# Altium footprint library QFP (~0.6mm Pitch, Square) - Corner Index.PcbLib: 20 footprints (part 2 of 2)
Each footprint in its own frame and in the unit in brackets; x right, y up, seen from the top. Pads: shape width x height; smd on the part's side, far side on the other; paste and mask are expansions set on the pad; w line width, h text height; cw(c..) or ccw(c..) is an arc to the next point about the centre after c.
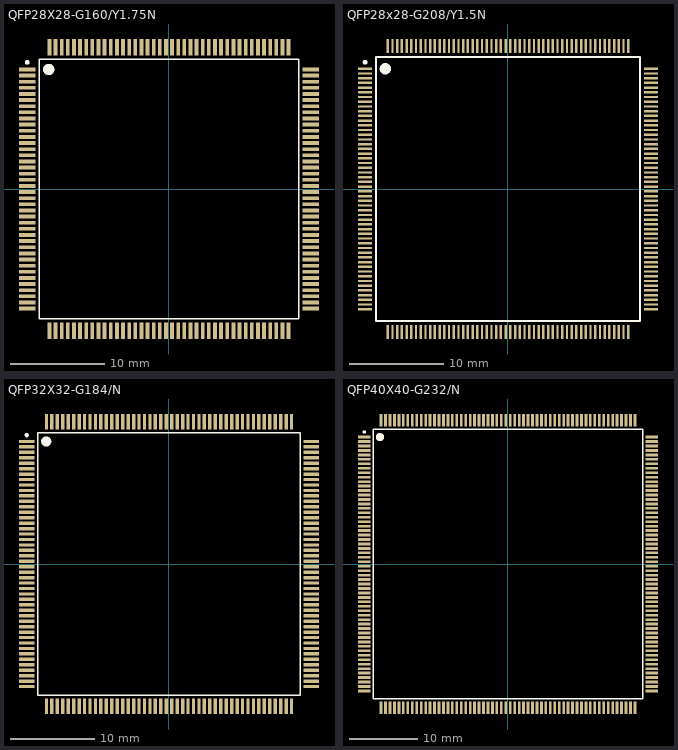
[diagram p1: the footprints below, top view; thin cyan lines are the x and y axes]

## QFP28X28-G160/Y1.75N [mm]
pads (160):
  rect 1.75x0.4 smd: 1(-15.025,12.675) 2(-15.025,12.025) 3(-15.025,11.375) 4(-15.025,10.725) 5(-15.025,10.075) 6(-15.025,9.425) 7(-15.025,8.775) 8(-15.025,8.125) 9(-15.025,7.475) 10(-15.025,6.825) 11(-15.025,6.175) 12(-15.025,5.525) 13(-15.025,4.875) 14(-15.025,4.225) 15(-15.025,3.575) 16(-15.025,2.925) 17(-15.025,2.275) 18(-15.025,1.625) 19(-15.025,0.975) 20(-15.025,0.325) 21(-15.025,-0.325) 22(-15.025,-0.975) 23(-15.025,-1.625) 24(-15.025,-2.275) 25(-15.025,-2.925) 26(-15.025,-3.575) 27(-15.025,-4.225) 28(-15.025,-4.875) 29(-15.025,-5.525) 30(-15.025,-6.175) 31(-15.025,-6.825) 32(-15.025,-7.475) 33(-15.025,-8.125) 34(-15.025,-8.775) 35(-15.025,-9.425) 36(-15.025,-10.075) 37(-15.025,-10.725) 38(-15.025,-11.375) 39(-15.025,-12.025) 40(-15.025,-12.675) 81(15.025,-12.675) 82(15.025,-12.025) 83(15.025,-11.375) 84(15.025,-10.725) 85(15.025,-10.075) 86(15.025,-9.425) 87(15.025,-8.775) 88(15.025,-8.125) 89(15.025,-7.475) 90(15.025,-6.825) 91(15.025,-6.175) 92(15.025,-5.525) 93(15.025,-4.875) 94(15.025,-4.225) 95(15.025,-3.575) 96(15.025,-2.925) 97(15.025,-2.275) 98(15.025,-1.625) 99(15.025,-0.975) 100(15.025,-0.325) 101(15.025,0.325) 102(15.025,0.975) 103(15.025,1.625) 104(15.025,2.275) 105(15.025,2.925) 106(15.025,3.575) 107(15.025,4.225) 108(15.025,4.875) 109(15.025,5.525) 110(15.025,6.175) 111(15.025,6.825) 112(15.025,7.475) 113(15.025,8.125) 114(15.025,8.775) 115(15.025,9.425) 116(15.025,10.075) 117(15.025,10.725) 118(15.025,11.375) 119(15.025,12.025) 120(15.025,12.675)
  rect 0.4x1.75 smd: 41(-12.675,-15.025) 42(-12.025,-15.025) 43(-11.375,-15.025) 44(-10.725,-15.025) 45(-10.075,-15.025) 46(-9.425,-15.025) 47(-8.775,-15.025) 48(-8.125,-15.025) 49(-7.475,-15.025) 50(-6.825,-15.025) 51(-6.175,-15.025) 52(-5.525,-15.025) 53(-4.875,-15.025) 54(-4.225,-15.025) 55(-3.575,-15.025) 56(-2.925,-15.025) 57(-2.275,-15.025) 58(-1.625,-15.025) 59(-0.975,-15.025) 60(-0.325,-15.025) 61(0.325,-15.025) 62(0.975,-15.025) 63(1.625,-15.025) 64(2.275,-15.025) 65(2.925,-15.025) 66(3.575,-15.025) 67(4.225,-15.025) 68(4.875,-15.025) 69(5.525,-15.025) 70(6.175,-15.025) 71(6.825,-15.025) 72(7.475,-15.025) 73(8.125,-15.025) 74(8.775,-15.025) 75(9.425,-15.025) 76(10.075,-15.025) 77(10.725,-15.025) 78(11.375,-15.025) 79(12.025,-15.025) 80(12.675,-15.025) 121(12.675,15.025) 122(12.025,15.025) 123(11.375,15.025) 124(10.725,15.025) 125(10.075,15.025) 126(9.425,15.025) 127(8.775,15.025) 128(8.125,15.025) 129(7.475,15.025) 130(6.825,15.025) 131(6.175,15.025) 132(5.525,15.025) 133(4.875,15.025) 134(4.225,15.025) 135(3.575,15.025) 136(2.925,15.025) 137(2.275,15.025) 138(1.625,15.025) 139(0.975,15.025) 140(0.325,15.025) 141(-0.325,15.025) 142(-0.975,15.025) 143(-1.625,15.025) 144(-2.275,15.025) 145(-2.925,15.025) 146(-3.575,15.025) 147(-4.225,15.025) 148(-4.875,15.025) 149(-5.525,15.025) 150(-6.175,15.025) 151(-6.825,15.025) 152(-7.475,15.025) 153(-8.125,15.025) 154(-8.775,15.025) 155(-9.425,15.025) 156(-10.075,15.025) 157(-10.725,15.025) 158(-11.375,15.025) 159(-12.025,15.025) 160(-12.675,15.025)
Top Overlay:
  circle w0.25: c-15.025,13.425 r0.125
  circle w0.6: c-12.75,12.675 r0.3
  lines w0.2: -13.75,-13.75 -13.75,13.75 13.75,13.75 13.75,-13.75 -13.75,-13.75

## QFP28x28-G208/Y1.5N [mm]
pads (208):
  rect 1.5x0.25 smd: 1(-15.15,12.75) 2(-15.15,12.25) 3(-15.15,11.75) 4(-15.15,11.25) 5(-15.15,10.75) 6(-15.15,10.25) 7(-15.15,9.75) 8(-15.15,9.25) 9(-15.15,8.75) 10(-15.15,8.25) 11(-15.15,7.75) 12(-15.15,7.25) 13(-15.15,6.75) 14(-15.15,6.25) 15(-15.15,5.75) 16(-15.15,5.25) 17(-15.15,4.75) 18(-15.15,4.25) 19(-15.15,3.75) 20(-15.15,3.25) 21(-15.15,2.75) 22(-15.15,2.25) 23(-15.15,1.75) 24(-15.15,1.25) 25(-15.15,0.75) 26(-15.15,0.25) 27(-15.15,-0.25) 28(-15.15,-0.75) 29(-15.15,-1.25) 30(-15.15,-1.75) 31(-15.15,-2.25) 32(-15.15,-2.75) 33(-15.15,-3.25) 34(-15.15,-3.75) 35(-15.15,-4.25) 36(-15.15,-4.75) 37(-15.15,-5.25) 38(-15.15,-5.75) 39(-15.15,-6.25) 40(-15.15,-6.75) 41(-15.15,-7.25) 42(-15.15,-7.75) 43(-15.15,-8.25) 44(-15.15,-8.75) 45(-15.15,-9.25) 46(-15.15,-9.75) 47(-15.15,-10.25) 48(-15.15,-10.75) 49(-15.15,-11.25) 50(-15.15,-11.75) 51(-15.15,-12.25) 52(-15.15,-12.75) 105(15.15,-12.75) 106(15.15,-12.25) 107(15.15,-11.75) 108(15.15,-11.25) 109(15.15,-10.75) 110(15.15,-10.25) 111(15.15,-9.75) 112(15.15,-9.25) 113(15.15,-8.75) 114(15.15,-8.25) 115(15.15,-7.75) 116(15.15,-7.25) 117(15.15,-6.75) 118(15.15,-6.25) 119(15.15,-5.75) 120(15.15,-5.25) 121(15.15,-4.75) 122(15.15,-4.25) 123(15.15,-3.75) 124(15.15,-3.25) 125(15.15,-2.75) 126(15.15,-2.25) 127(15.15,-1.75) 128(15.15,-1.25) 129(15.15,-0.75) 130(15.15,-0.25) 131(15.15,0.25) 132(15.15,0.75) 133(15.15,1.25) 134(15.15,1.75) 135(15.15,2.25) 136(15.15,2.75) 137(15.15,3.25) 138(15.15,3.75) 139(15.15,4.25) 140(15.15,4.75) 141(15.15,5.25) 142(15.15,5.75) 143(15.15,6.25) 144(15.15,6.75) 145(15.15,7.25) 146(15.15,7.75) 147(15.15,8.25) 148(15.15,8.75) 149(15.15,9.25) 150(15.15,9.75) 151(15.15,10.25) 152(15.15,10.75) 153(15.15,11.25) 154(15.15,11.75) 155(15.15,12.25) 156(15.15,12.75)
  rect 0.25x1.5 smd: 53(-12.75,-15.15) 54(-12.25,-15.15) 55(-11.75,-15.15) 56(-11.25,-15.15) 57(-10.75,-15.15) 58(-10.25,-15.15) 59(-9.75,-15.15) 60(-9.25,-15.15) 61(-8.75,-15.15) 62(-8.25,-15.15) 63(-7.75,-15.15) 64(-7.25,-15.15) 65(-6.75,-15.15) 66(-6.25,-15.15) 67(-5.75,-15.15) 68(-5.25,-15.15) 69(-4.75,-15.15) 70(-4.25,-15.15) 71(-3.75,-15.15) 72(-3.25,-15.15) 73(-2.75,-15.15) 74(-2.25,-15.15) 75(-1.75,-15.15) 76(-1.25,-15.15) 77(-0.75,-15.15) 78(-0.25,-15.15) 79(0.25,-15.15) 80(0.75,-15.15) 81(1.25,-15.15) 82(1.75,-15.15) 83(2.25,-15.15) 84(2.75,-15.15) 85(3.25,-15.15) 86(3.75,-15.15) 87(4.25,-15.15) 88(4.75,-15.15) 89(5.25,-15.15) 90(5.75,-15.15) 91(6.25,-15.15) 92(6.75,-15.15) 93(7.25,-15.15) 94(7.75,-15.15) 95(8.25,-15.15) 96(8.75,-15.15) 97(9.25,-15.15) 98(9.75,-15.15) 99(10.25,-15.15) 100(10.75,-15.15) 101(11.25,-15.15) 102(11.75,-15.15) 103(12.25,-15.15) 104(12.75,-15.15) 157(12.75,15.15) 158(12.25,15.15) 159(11.75,15.15) 160(11.25,15.15) 161(10.75,15.15) 162(10.25,15.15) 163(9.75,15.15) 164(9.25,15.15) 165(8.75,15.15) 166(8.25,15.15) 167(7.75,15.15) 168(7.25,15.15) 169(6.75,15.15) 170(6.25,15.15) 171(5.75,15.15) 172(5.25,15.15) 173(4.75,15.15) 174(4.25,15.15) 175(3.75,15.15) 176(3.25,15.15) 177(2.75,15.15) 178(2.25,15.15) 179(1.75,15.15) 180(1.25,15.15) 181(0.75,15.15) 182(0.25,15.15) 183(-0.25,15.15) 184(-0.75,15.15) 185(-1.25,15.15) 186(-1.75,15.15) 187(-2.25,15.15) 188(-2.75,15.15) 189(-3.25,15.15) 190(-3.75,15.15) 191(-4.25,15.15) 192(-4.75,15.15) 193(-5.25,15.15) 194(-5.75,15.15) 195(-6.25,15.15) 196(-6.75,15.15) 197(-7.25,15.15) 198(-7.75,15.15) 199(-8.25,15.15) 200(-8.75,15.15) 201(-9.25,15.15) 202(-9.75,15.15) 203(-10.25,15.15) 204(-10.75,15.15) 205(-11.25,15.15) 206(-11.75,15.15) 207(-12.25,15.15) 208(-12.75,15.15)
Top Overlay:
  circle w0.25: c-15.15,13.425 r0.125
  circle w0.6: c-13,12.75 r0.3
  lines w0.2: -14,-14 -14,14 14,14 14,-14 -14,-14

## QFP32X32-G184/N [mm]
pads (184):
  rect 1.85x0.4 smd: 1(-16.975,14.625) 2(-16.975,13.975) 3(-16.975,13.325) 4(-16.975,12.675) 5(-16.975,12.025) 6(-16.975,11.375) 7(-16.975,10.725) 8(-16.975,10.075) 9(-16.975,9.425) 10(-16.975,8.775) 11(-16.975,8.125) 12(-16.975,7.475) 13(-16.975,6.825) 14(-16.975,6.175) 15(-16.975,5.525) 16(-16.975,4.875) 17(-16.975,4.225) 18(-16.975,3.575) 19(-16.975,2.925) 20(-16.975,2.275) 21(-16.975,1.625) 22(-16.975,0.975) 23(-16.975,0.325) 24(-16.975,-0.325) 25(-16.975,-0.975) 26(-16.975,-1.625) 27(-16.975,-2.275) 28(-16.975,-2.925) 29(-16.975,-3.575) 30(-16.975,-4.225) 31(-16.975,-4.875) 32(-16.975,-5.525) 33(-16.975,-6.175) 34(-16.975,-6.825) 35(-16.975,-7.475) 36(-16.975,-8.125) 37(-16.975,-8.775) 38(-16.975,-9.425) 39(-16.975,-10.075) 40(-16.975,-10.725) 41(-16.975,-11.375) 42(-16.975,-12.025) 43(-16.975,-12.675) 44(-16.975,-13.325) 45(-16.975,-13.975) 46(-16.975,-14.625) 93(16.975,-14.625) 94(16.975,-13.975) 95(16.975,-13.325) 96(16.975,-12.675) 97(16.975,-12.025) 98(16.975,-11.375) 99(16.975,-10.725) 100(16.975,-10.075) 101(16.975,-9.425) 102(16.975,-8.775) 103(16.975,-8.125) 104(16.975,-7.475) 105(16.975,-6.825) 106(16.975,-6.175) 107(16.975,-5.525) 108(16.975,-4.875) 109(16.975,-4.225) 110(16.975,-3.575) 111(16.975,-2.925) 112(16.975,-2.275) 113(16.975,-1.625) 114(16.975,-0.975) 115(16.975,-0.325) 116(16.975,0.325) 117(16.975,0.975) 118(16.975,1.625) 119(16.975,2.275) 120(16.975,2.925) 121(16.975,3.575) 122(16.975,4.225) 123(16.975,4.875) 124(16.975,5.525) 125(16.975,6.175) 126(16.975,6.825) 127(16.975,7.475) 128(16.975,8.125) 129(16.975,8.775) 130(16.975,9.425) 131(16.975,10.075) 132(16.975,10.725) 133(16.975,11.375) 134(16.975,12.025) 135(16.975,12.675) 136(16.975,13.325) 137(16.975,13.975) 138(16.975,14.625)
  rect 0.4x1.85 smd: 47(-14.625,-16.975) 48(-13.975,-16.975) 49(-13.325,-16.975) 50(-12.675,-16.975) 51(-12.025,-16.975) 52(-11.375,-16.975) 53(-10.725,-16.975) 54(-10.075,-16.975) 55(-9.425,-16.975) 56(-8.775,-16.975) 57(-8.125,-16.975) 58(-7.475,-16.975) 59(-6.825,-16.975) 60(-6.175,-16.975) 61(-5.525,-16.975) 62(-4.875,-16.975) 63(-4.225,-16.975) 64(-3.575,-16.975) 65(-2.925,-16.975) 66(-2.275,-16.975) 67(-1.625,-16.975) 68(-0.975,-16.975) 69(-0.325,-16.975) 70(0.325,-16.975) 71(0.975,-16.975) 72(1.625,-16.975) 73(2.275,-16.975) 74(2.925,-16.975) 75(3.575,-16.975) 76(4.225,-16.975) 77(4.875,-16.975) 78(5.525,-16.975) 79(6.175,-16.975) 80(6.825,-16.975) 81(7.475,-16.975) 82(8.125,-16.975) 83(8.775,-16.975) 84(9.425,-16.975) 85(10.075,-16.975) 86(10.725,-16.975) 87(11.375,-16.975) 88(12.025,-16.975) 89(12.675,-16.975) 90(13.325,-16.975) 91(13.975,-16.975) 92(14.625,-16.975) 139(14.625,16.975) 140(13.975,16.975) 141(13.325,16.975) 142(12.675,16.975) 143(12.025,16.975) 144(11.375,16.975) 145(10.725,16.975) 146(10.075,16.975) 147(9.425,16.975) 148(8.775,16.975) 149(8.125,16.975) 150(7.475,16.975) 151(6.825,16.975) 152(6.175,16.975) 153(5.525,16.975) 154(4.875,16.975) 155(4.225,16.975) 156(3.575,16.975) 157(2.925,16.975) 158(2.275,16.975) 159(1.625,16.975) 160(0.975,16.975) 161(0.325,16.975) 162(-0.325,16.975) 163(-0.975,16.975) 164(-1.625,16.975) 165(-2.275,16.975) 166(-2.925,16.975) 167(-3.575,16.975) 168(-4.225,16.975) 169(-4.875,16.975) 170(-5.525,16.975) 171(-6.175,16.975) 172(-6.825,16.975) 173(-7.475,16.975) 174(-8.125,16.975) 175(-8.775,16.975) 176(-9.425,16.975) 177(-10.075,16.975) 178(-10.725,16.975) 179(-11.375,16.975) 180(-12.025,16.975) 181(-12.675,16.975) 182(-13.325,16.975) 183(-13.975,16.975) 184(-14.625,16.975)
Top Overlay:
  circle w0.25: c-16.975,15.375 r0.125
  circle w0.6: c-14.65,14.625 r0.3
  lines w0.2: -15.65,-15.65 15.65,-15.65 15.65,15.65 -15.65,15.65 -15.65,-15.65

## QFP40X40-G232/N [mm]
pads (232):
  rect 1.8x0.4 smd: 1(-21,18.525) 2(-21,17.875) 3(-21,17.225) 4(-21,16.575) 5(-21,15.925) 6(-21,15.275) 7(-21,14.625) 8(-21,13.975) 9(-21,13.325) 10(-21,12.675) 11(-21,12.025) 12(-21,11.375) 13(-21,10.725) 14(-21,10.075) 15(-21,9.425) 16(-21,8.775) 17(-21,8.125) 18(-21,7.475) 19(-21,6.825) 20(-21,6.175) 21(-21,5.525) 22(-21,4.875) 23(-21,4.225) 24(-21,3.575) 25(-21,2.925) 26(-21,2.275) 27(-21,1.625) 28(-21,0.975) 29(-21,0.325) 30(-21,-0.325) 31(-21,-0.975) 32(-21,-1.625) 33(-21,-2.275) 34(-21,-2.925) 35(-21,-3.575) 36(-21,-4.225) 37(-21,-4.875) 38(-21,-5.525) 39(-21,-6.175) 40(-21,-6.825) 41(-21,-7.475) 42(-21,-8.125) 43(-21,-8.775) 44(-21,-9.425) 45(-21,-10.075) 46(-21,-10.725) 47(-21,-11.375) 48(-21,-12.025) 49(-21,-12.675) 50(-21,-13.325) 51(-21,-13.975) 52(-21,-14.625) 53(-21,-15.275) 54(-21,-15.925) 55(-21,-16.575) 56(-21,-17.225) 57(-21,-17.875) 58(-21,-18.525) 117(21,-18.525) 118(21,-17.875) 119(21,-17.225) 120(21,-16.575) 121(21,-15.925) 122(21,-15.275) 123(21,-14.625) 124(21,-13.975) 125(21,-13.325) 126(21,-12.675) 127(21,-12.025) 128(21,-11.375) 129(21,-10.725) 130(21,-10.075) 131(21,-9.425) 132(21,-8.775) 133(21,-8.125) 134(21,-7.475) 135(21,-6.825) 136(21,-6.175) 137(21,-5.525) 138(21,-4.875) 139(21,-4.225) 140(21,-3.575) 141(21,-2.925) 142(21,-2.275) 143(21,-1.625) 144(21,-0.975) 145(21,-0.325) 146(21,0.325) 147(21,0.975) 148(21,1.625) 149(21,2.275) 150(21,2.925) 151(21,3.575) 152(21,4.225) 153(21,4.875) 154(21,5.525) 155(21,6.175) 156(21,6.825) 157(21,7.475) 158(21,8.125) 159(21,8.775) 160(21,9.425) 161(21,10.075) 162(21,10.725) 163(21,11.375) 164(21,12.025) 165(21,12.675) 166(21,13.325) 167(21,13.975) 168(21,14.625) 169(21,15.275) 170(21,15.925) 171(21,16.575) 172(21,17.225) 173(21,17.875) 174(21,18.525)
  rect 0.4x1.8 smd: 59(-18.525,-21) 60(-17.875,-21) 61(-17.225,-21) 62(-16.575,-21) 63(-15.925,-21) 64(-15.275,-21) 65(-14.625,-21) 66(-13.975,-21) 67(-13.325,-21) 68(-12.675,-21) 69(-12.025,-21) 70(-11.375,-21) 71(-10.725,-21) 72(-10.075,-21) 73(-9.425,-21) 74(-8.775,-21) 75(-8.125,-21) 76(-7.475,-21) 77(-6.825,-21) 78(-6.175,-21) 79(-5.525,-21) 80(-4.875,-21) 81(-4.225,-21) 82(-3.575,-21) 83(-2.925,-21) 84(-2.275,-21) 85(-1.625,-21) 86(-0.975,-21) 87(-0.325,-21) 88(0.325,-21) 89(0.975,-21) 90(1.625,-21) 91(2.275,-21) 92(2.925,-21) 93(3.575,-21) 94(4.225,-21) 95(4.875,-21) 96(5.525,-21) 97(6.175,-21) 98(6.825,-21) 99(7.475,-21) 100(8.125,-21) 101(8.775,-21) 102(9.425,-21) 103(10.075,-21) 104(10.725,-21) 105(11.375,-21) 106(12.025,-21) 107(12.675,-21) 108(13.325,-21) 109(13.975,-21) 110(14.625,-21) 111(15.275,-21) 112(15.925,-21) 113(16.575,-21) 114(17.225,-21) 115(17.875,-21) 116(18.525,-21) 175(18.525,21) 176(17.875,21) 177(17.225,21) 178(16.575,21) 179(15.925,21) 180(15.275,21) 181(14.625,21) 182(13.975,21) 183(13.325,21) 184(12.675,21) 185(12.025,21) 186(11.375,21) 187(10.725,21) 188(10.075,21) 189(9.425,21) 190(8.775,21) 191(8.125,21) 192(7.475,21) 193(6.825,21) 194(6.175,21) 195(5.525,21) 196(4.875,21) 197(4.225,21) 198(3.575,21) 199(2.925,21) 200(2.275,21) 201(1.625,21) 202(0.975,21) 203(0.325,21) 204(-0.325,21) 205(-0.975,21) 206(-1.625,21) 207(-2.275,21) 208(-2.925,21) 209(-3.575,21) 210(-4.225,21) 211(-4.875,21) 212(-5.525,21) 213(-6.175,21) 214(-6.825,21) 215(-7.475,21) 216(-8.125,21) 217(-8.775,21) 218(-9.425,21) 219(-10.075,21) 220(-10.725,21) 221(-11.375,21) 222(-12.025,21) 223(-12.675,21) 224(-13.325,21) 225(-13.975,21) 226(-14.625,21) 227(-15.275,21) 228(-15.925,21) 229(-16.575,21) 230(-17.225,21) 231(-17.875,21) 232(-18.525,21)
Top Overlay:
  circle w0.6: c-18.7,18.525 r0.3
  circle w0.25: c-21,19.275 r0.125
  lines w0.2: -19.7,-19.7 -19.7,19.7 19.7,19.7 19.7,-19.7 -19.7,-19.7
